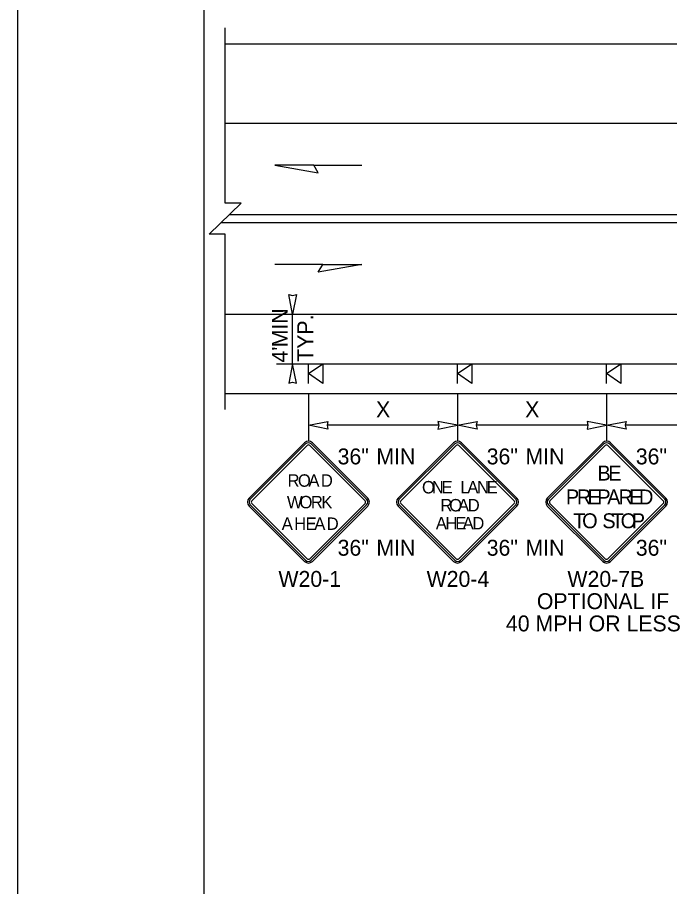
# Model space of a CAD drawing. Extents: x 99998.9 to 100095.7, y 99995 to 100010.7.
# Drawn here: x 99999.062 to 100002.344, y 100003.251 to 100007.625 of the extents above; entities that cross this region are included whole.
import ezdxf

# ---------------------------------------------------------------- set-up
doc = ezdxf.new("R2010")
doc.units = 0
for name, color, linetype in [('RD_ED_ShoulderPavedEdge', 7, 'Continuous'), ('RD_MK_LineDblYellowCenter', 7, 'Continuous'), ('RD_MK_LineEdgeWhite', 7, 'Continuous'), ('SH_GI_PlotLimits', 7, 'Continuous'), ('SH_GI_SheetBorder', 7, 'Continuous'), ('TR_SN_ConstructionSigns', 7, 'Continuous'), ('TR_WZ_PortableSignMountBlk-Org', 7, 'Continuous'), ('TR_WZ_WorkZoneDetails', 7, 'Continuous'), ('TR_WZ_WorkZoneTextCurrent', 7, 'Continuous')]:
    doc.layers.add(name, color=color, linetype=linetype)

msp = doc.modelspace()

# ---------------------------------------------------------------- linework, layer by layer
at = {"layer": 'RD_ED_ShoulderPavedEdge'}
for p, q in [((100000.1076, 100007.4923), (100015.6424, 100007.4923)), ((100000.1076, 100005.7323), (100015.6424, 100005.7323))]:
    msp.add_line(p, q, dxfattribs=at)
at = {"layer": 'RD_MK_LineDblYellowCenter'}
for p, q in [((100000.1282, 100006.6323), (100003.4767, 100006.6323)), ((100000.0869, 100006.5923), (100003.4767, 100006.5923))]:
    msp.add_line(p, q, dxfattribs=at)
at = {"layer": 'RD_MK_LineEdgeWhite'}
for p, q in [((100000.1076, 100007.0923), (100015.6424, 100007.0923)), ((100000.1076, 100006.1323), (100015.6424, 100006.1323))]:
    msp.add_line(p, q, dxfattribs=at)
at = {"layer": 'SH_GI_PlotLimits'}
msp.add_lwpolyline([(99999.0625, 99999.6875), (100016.0625, 99999.6875), (100016.0625, 100010.6875), (99999.0625, 100010.6875)], close=True, dxfattribs=at)
at = {"layer": 'SH_GI_SheetBorder'}
msp.add_line((100000, 100010.375), (100000, 100000), dxfattribs=at)
at = {"layer": 'TR_SN_ConstructionSigns'}
for p, q in [((100000.5068, 100005.4841), (100000.2283, 100005.2057)), ((100000.825, 100005.2057), (100000.5465, 100005.4841)), ((100001.2568, 100005.4841), (100000.9783, 100005.2057)), ((100001.575, 100005.2057), (100001.2965, 100005.4841)), ((100002.0068, 100005.4841), (100001.7283, 100005.2057)), ((100002.325, 100005.2057), (100002.0465, 100005.4841)), ((100000.5123, 100005.4786), (100000.2339, 100005.2001)), ((100000.2416, 100005.1924), (100000.52, 100005.4708)), ((100000.5333, 100005.4708), (100000.8117, 100005.1924)), ((100000.8194, 100005.2001), (100000.541, 100005.4786)), ((100001.2623, 100005.4786), (100000.9839, 100005.2001)), ((100000.9916, 100005.1924), (100001.27, 100005.4708)), ((100001.2833, 100005.4708), (100001.5617, 100005.1924)), ((100001.5694, 100005.2001), (100001.291, 100005.4786)), ((100002.0123, 100005.4786), (100001.7339, 100005.2001)), ((100001.7416, 100005.1924), (100002.02, 100005.4708)), ((100002.0333, 100005.4708), (100002.3117, 100005.1924)), ((100002.3194, 100005.2001), (100002.041, 100005.4786)), ((100000.52, 100004.9007), (100000.2416, 100005.1792)), ((100000.8117, 100005.1792), (100000.5333, 100004.9007)), ((100001.27, 100004.9007), (100000.9916, 100005.1792)), ((100001.5617, 100005.1792), (100001.2833, 100004.9007)), ((100002.02, 100004.9007), (100001.7416, 100005.1792)), ((100002.3117, 100005.1792), (100002.0333, 100004.9007)), ((100000.2283, 100005.1659), (100000.5068, 100004.8875)), ((100000.2339, 100005.1714), (100000.5123, 100004.893)), ((100000.541, 100004.893), (100000.8194, 100005.1714)), ((100000.5465, 100004.8875), (100000.825, 100005.1659)), ((100000.9783, 100005.1659), (100001.2568, 100004.8875)), ((100000.9839, 100005.1714), (100001.2623, 100004.893)), ((100001.291, 100004.893), (100001.5694, 100005.1714)), ((100001.2965, 100004.8875), (100001.575, 100005.1659)), ((100001.7283, 100005.1659), (100002.0068, 100004.8875)), ((100001.7339, 100005.1714), (100002.0123, 100004.893)), ((100002.041, 100004.893), (100002.3194, 100005.1714)), ((100002.0465, 100004.8875), (100002.325, 100005.1659))]:
    msp.add_line(p, q, dxfattribs=at)
for centre, radius, start, end in [((100000.5267, 100005.4642), 0.0281, 45, 135), ((100000.5267, 100005.4642), 0.0203, 45, 135), ((100001.2767, 100005.4642), 0.0281, 45, 135), ((100001.2767, 100005.4642), 0.0203, 45, 135), ((100002.0267, 100005.4642), 0.0281, 45, 135), ((100002.0267, 100005.4642), 0.0203, 45, 135), ((100000.5267, 100005.4642), 0.00937, 45, 135), ((100001.2767, 100005.4642), 0.00937, 45, 135), ((100002.0267, 100005.4642), 0.00937, 45, 135), ((100000.2482, 100005.1858), 0.0281, 135, 225), ((100000.2482, 100005.1858), 0.0203, 135, 225), ((100000.2482, 100005.1858), 0.00937, 135, 225), ((100000.8051, 100005.1858), 0.00937, 315, 45), ((100000.8051, 100005.1858), 0.0203, 315, 45), ((100000.8051, 100005.1858), 0.0281, 315, 45), ((100000.9982, 100005.1858), 0.0281, 135, 225), ((100000.9982, 100005.1858), 0.0203, 135, 225), ((100000.9982, 100005.1858), 0.00937, 135, 225), ((100001.5551, 100005.1858), 0.00937, 315, 45), ((100001.5551, 100005.1858), 0.0203, 315, 45), ((100001.5551, 100005.1858), 0.0281, 315, 45), ((100001.7482, 100005.1858), 0.0281, 135, 225), ((100001.7482, 100005.1858), 0.0203, 135, 225), ((100001.7482, 100005.1858), 0.00937, 135, 225), ((100002.3051, 100005.1858), 0.00937, 315, 45), ((100002.3051, 100005.1858), 0.0203, 315, 45), ((100002.3051, 100005.1858), 0.0281, 315, 45), ((100000.5267, 100004.9074), 0.0281, 225, 315), ((100000.5267, 100004.9074), 0.0203, 225, 315), ((100000.5267, 100004.9074), 0.00937, 225, 315), ((100001.2767, 100004.9074), 0.0281, 225, 315), ((100001.2767, 100004.9074), 0.0203, 225, 315), ((100001.2767, 100004.9074), 0.00937, 225, 315), ((100002.0267, 100004.9074), 0.0281, 225, 315), ((100002.0267, 100004.9074), 0.0203, 225, 315), ((100002.0267, 100004.9074), 0.00937, 225, 315)]:
    msp.add_arc(centre, radius, start, end, dxfattribs=at)
at = {"layer": 'TR_WZ_PortableSignMountBlk-Org'}
for p, q in [((100000.5267, 100005.7824), (100000.5267, 100005.8824)), ((100001.2767, 100005.7824), (100001.2767, 100005.8824)), ((100002.0267, 100005.7824), (100002.0267, 100005.8824))]:
    msp.add_line(p, q, dxfattribs=at)
for points in [[(100000.5267, 100005.8323), (100000.5985, 100005.8824), (100000.5985, 100005.7824)], [(100001.2767, 100005.8323), (100001.3485, 100005.8824), (100001.3485, 100005.7824)], [(100002.0267, 100005.8323), (100002.0985, 100005.8824), (100002.0985, 100005.7824)]]:
    msp.add_lwpolyline(points, close=True, dxfattribs=at)
at = {"layer": 'TR_WZ_WorkZoneDetails'}
for p, q in [((100000.5541, 100006.8816), (100000.7952, 100006.8816)), ((100000.5987, 100006.3816), (100000.3576, 100006.3816)), ((100000.3667, 100006.1323), (100000.5267, 100006.1323)), ((100000.4467, 100005.8824), (100000.4467, 100006.1323)), ((100000.3667, 100005.8824), (100000.5267, 100005.8824)), ((100000.5267, 100005.8824), (100003.5267, 100005.8824)), ((100000.5267, 100005.7326), (100000.5267, 100005.4923)), ((100001.2767, 100005.7323), (100001.2767, 100005.4923)), ((100002.0267, 100005.7323), (100002.0267, 100005.4923)), ((100001.1829, 100005.5723), (100000.6204, 100005.5723)), ((100001.9329, 100005.5723), (100001.3704, 100005.5723)), ((100002.6829, 100005.5723), (100002.1204, 100005.5723))]:
    msp.add_line(p, q, dxfattribs=at)
msp.add_lwpolyline([(100000.1076, 100005.6523), (100000.1076, 100006.5349), (100000.0275, 100006.5349), (100000.1876, 100006.6898), (100000.1076, 100006.6898), (100000.1076, 100007.5723)], dxfattribs=at)
for points in [[(100000.3576, 100006.8816), (100000.5764, 100006.843), (100000.5541, 100006.8816)], [(100000.7952, 100006.3816), (100000.5764, 100006.343), (100000.5987, 100006.3816)], [(100000.4467, 100006.1323), (100000.4274, 100006.2306), (100000.4467, 100006.2261), (100000.4659, 100006.2306)], [(100000.4467, 100005.8824), (100000.4274, 100005.7841), (100000.4467, 100005.7887), (100000.4659, 100005.7841)], [(100000.5267, 100005.5723), (100000.6249, 100005.5916), (100000.6204, 100005.5723), (100000.6249, 100005.5531)], [(100001.2767, 100005.5723), (100001.1784, 100005.5916), (100001.1829, 100005.5723), (100001.1784, 100005.5531)], [(100001.2767, 100005.5723), (100001.3749, 100005.5916), (100001.3704, 100005.5723), (100001.3749, 100005.5531)], [(100002.0267, 100005.5723), (100001.9284, 100005.5916), (100001.9329, 100005.5723), (100001.9284, 100005.5531)], [(100002.0267, 100005.5723), (100002.1249, 100005.5916), (100002.1204, 100005.5723), (100002.1249, 100005.5531)]]:
    msp.add_lwpolyline(points, close=True, dxfattribs=at)

# ---------------------------------------------------------------- texts
at = {"layer": 'TR_SN_ConstructionSigns'}
for s, p in [('36"', (100000.6734, 100005.3756)), ('MIN', (100000.8684, 100005.3756)), ('36"', (100001.4234, 100005.3756)), ('MIN', (100001.6184, 100005.3756)), ('36"', (100002.1734, 100005.3756)), ('36"', (100000.6734, 100004.916)), ('MIN', (100000.8684, 100004.916)), ('36"', (100001.4234, 100004.916)), ('MIN', (100001.6184, 100004.916)), ('36"', (100002.1734, 100004.916)), ('W20-1', (100000.3757, 100004.7592)), ('W20-4', (100001.1212, 100004.7592)), ('W20-7B', (100001.8296, 100004.7592)), ('OPTIONAL IF', (100001.6757, 100004.6472)), ('40 MPH OR LESS', (100001.5202, 100004.5352))]:
    msp.add_text(s, height=0.08, rotation=360, dxfattribs=at).set_placement(p)
for s, height, p in [('B', 0.075, (100001.9804, 100005.2943)), ('E', 0.075, (100002.0347, 100005.2943)), ('R', 0.0625, (100000.4216, 100005.2631)), ('O', 0.0625, (100000.4737, 100005.2631)), ('A', 0.0625, (100000.5265, 100005.2631)), ('D', 0.0625, (100000.5892, 100005.2631)), ('O', 0.0625, (100001.0979, 100005.2295)), ('N', 0.0625, (100001.1473, 100005.2295)), ('E', 0.0625, (100001.196, 100005.2295)), ('L', 0.0625, (100001.2904, 100005.2295)), ('A', 0.0625, (100001.326, 100005.2295)), ('N', 0.0625, (100001.3748, 100005.2295)), ('E', 0.0625, (100001.4235, 100005.2295)), ('P', 0.075, (100001.8218, 100005.1743)), ('R', 0.075, (100001.877, 100005.1743)), ('E', 0.075, (100001.9302, 100005.1743)), ('P', 0.075, (100001.9797, 100005.1743)), ('A', 0.075, (100002.0296, 100005.1743)), ('R', 0.075, (100002.0868, 100005.1743)), ('E', 0.075, (100002.1401, 100005.1743)), ('D', 0.075, (100002.1896, 100005.1743)), ('W', 0.0625, (100000.4183, 100005.1545)), ('O', 0.0625, (100000.4816, 100005.1545)), ('R', 0.0625, (100000.5388, 100005.1545)), ('K', 0.0625, (100000.5912, 100005.1545)), ('R', 0.0625, (100001.1904, 100005.1389)), ('O', 0.0625, (100001.2348, 100005.1389)), ('A', 0.0625, (100001.2792, 100005.1389)), ('D', 0.0625, (100001.3279, 100005.1389)), ('A', 0.0625, (100000.3923, 100005.046)), ('H', 0.0625, (100000.4548, 100005.046)), ('E', 0.0625, (100000.5123, 100005.046)), ('A', 0.0625, (100000.556, 100005.046)), ('D', 0.0625, (100000.6185, 100005.046)), ('A', 0.0625, (100001.1673, 100005.0483)), ('H', 0.0625, (100001.216, 100005.0483)), ('E', 0.0625, (100001.2648, 100005.0483)), ('A', 0.0625, (100001.3023, 100005.0483)), ('D', 0.0625, (100001.351, 100005.0483)), ('T', 0.075, (100001.8584, 100005.0543)), ('O', 0.075, (100001.9035, 100005.0543)), ('S', 0.075, (100002.005, 100005.0543)), ('T', 0.075, (100002.0521, 100005.0543)), ('O', 0.075, (100002.0972, 100005.0543)), ('P', 0.075, (100002.1529, 100005.0543))]:
    msp.add_text(s, height=height, dxfattribs=at).set_placement(p)
at = {"layer": 'TR_WZ_WorkZoneTextCurrent'}
for s, rotation, p in [('MIN', 90, (100000.4227, 100005.9648)), ('TYP.', 90, (100000.5507, 100005.892)), ("4'", 90, (100000.4227, 100005.8883)), ('X', 360, (100000.8669, 100005.6123)), ('X', 360, (100001.6169, 100005.6123))]:
    msp.add_text(s, height=0.08, rotation=rotation, dxfattribs=at).set_placement(p)

doc.saveas('drawing.dxf')
